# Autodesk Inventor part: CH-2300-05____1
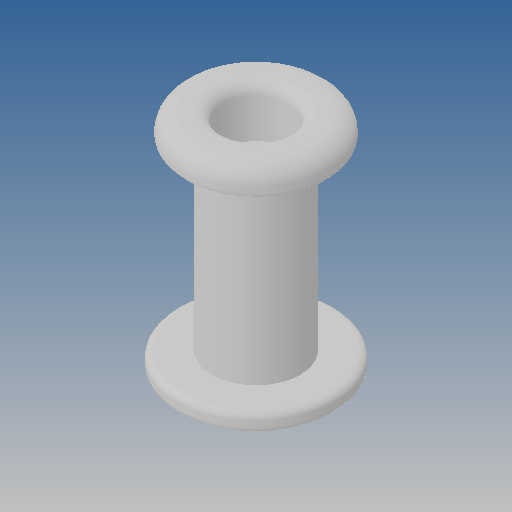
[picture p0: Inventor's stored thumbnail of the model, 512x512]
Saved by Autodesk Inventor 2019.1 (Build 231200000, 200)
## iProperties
Created: 2012-09
Part Number: CH-2300-05____1
Material: Ogólny
Document SubType Name: Modeling
Designer: CADENGINEERING4
Density: 1 g/cm^3
Appearance: Domyślna
Author: CADENGINEERING4
Revision Number: ÈÎºÎ
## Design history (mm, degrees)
feature "NONE"
node "Bryła1"
